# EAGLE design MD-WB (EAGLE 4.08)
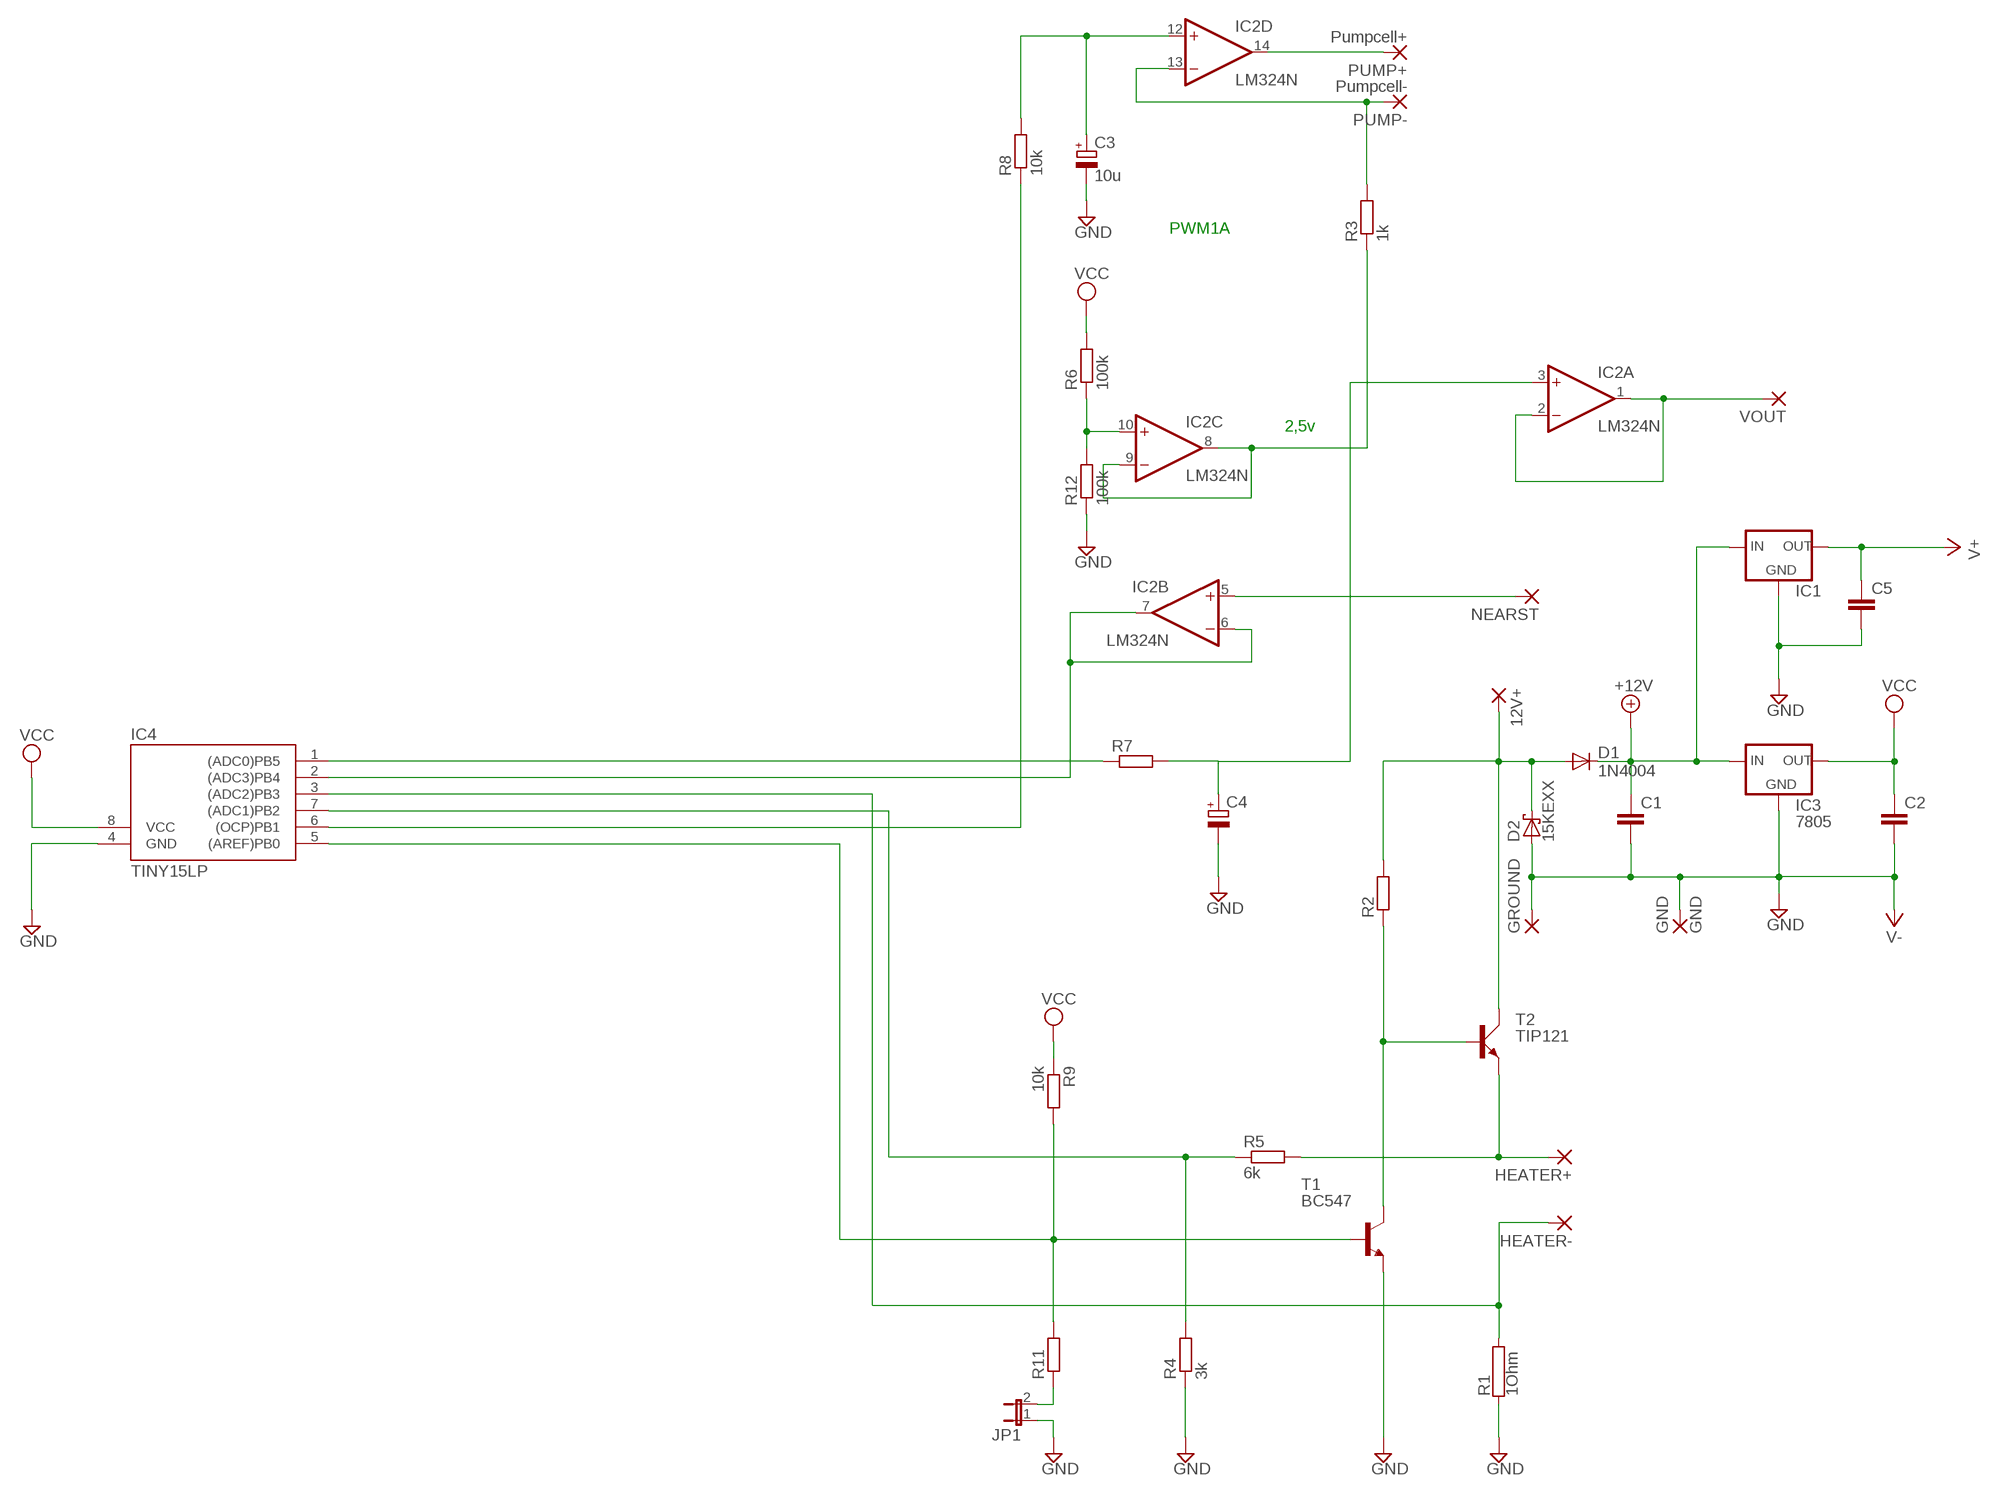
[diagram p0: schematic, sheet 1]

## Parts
12V+  2,15/1,0  [2,15/1,0]
C1  C-EU050-035X075  [C050-035X075]
C2  C-EU050-035X075  [C050-035X075]
C3  10u  CPOL-EUE2-4  [E2-4]
C4  CPOL-EUE2-4  [E2-4]
C5  C-EU050-035X075  [C050-035X075]
D1  1N4004  [DO41-10]
D2  15KEXX  [CB429-17]
GND  GND  2,54/1,0  [2,54/1,0]
GROUND  2,15/1,0  [2,15/1,0]
HEATER+  2,15/1,0  [2,15/1,0]
HEATER-  2,15/1,0  [2,15/1,0]
IC1  78LXX  [78LXX]
IC2  LM324N  [DIL14]
IC3  7805  78LXX  [78LXX]
IC4  TINY15LP  [DIL08]
JP1  JP1E  [JP1]
NEARST  2,15/1,0  [2,15/1,0]
PUMP+  Pumpcell+  2,54/1,0  [2,54/1,0]
PUMP-  Pumpcell-  2,54/1,0  [2,54/1,0]
R1  1Ohm  RKH214-8R  [KH214R-8]
R2  R-EU_0207/7  [0207/7]
R3  1k  R-EU_0207/7  [0207/7]
R4  3k  R-EU_0207/7  [0207/7]
R5  6k  R-EU_0207/7  [0207/7]
R6  100k  R-EU_0207/7  [0207/7]
R7  R-EU_0207/7  [0207/7]
R8  10k  R-EU_0207/7  [0207/7]
R9  10k  R-EU_0207/7  [0207/7]
R11  R-EU_0207/7  [0207/7]
R12  100k  R-EU_0207/7  [0207/7]
T1  BC547  [TO92]
T2  TIP121  MJE3055  [TO220AV]
VOUT  2,54/1,0  [2,54/1,0]

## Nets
+12V: C1.1 D1.C IC1.IN IC3.IN
GND: C1.2 C2.2 C3.- C4.- C5.2 D2.A GND.1(P) GROUND.1(P) IC1.GND IC3.GND IC4.4(GND) JP1.1 R1.1 R4.1 R12.1 T1.1(E) ; supply symbol labelled V-
N$1: IC2.13(D:-IN) PUMP-.1(P) R3.2
N$2: IC4.5((AREF)PB0) R9.2 R11.2 T1.2(B)
N$3: IC2.10(C:+IN) R6.1 R12.2
N$4: IC4.6((OCP)PB1) R8.1
N$5: C4.+ IC2.3(A:+IN) R7.2
N$6: R2.1 T1.3(C) T2.B
N$7: IC2.8(C:OUT) IC2.9(C:-IN) R3.1
N$8: IC2.1(A:OUT) IC2.2(A:-IN) VOUT.1(P)
N$9: C3.+ IC2.12(D:+IN) R8.2
N$10: IC4.1((ADC0)PB5) R7.1
N$11: IC2.6(B:-IN) IC2.7(B:OUT) IC4.2((ADC3)PB4)
N$13: JP1.2 R11.1
N$14: 12V+.1(P) D1.A D2.C R2.2 T2.C
N$26: IC4.7((ADC1)PB2) R4.2 R5.1
N$30: IC2.14(D:OUT) PUMP+.1(P)
N$31: HEATER-.1(P) IC4.3((ADC2)PB3) R1.2
N$36: IC2.5(B:+IN) NEARST.1(P)
N$37: HEATER+.1(P) R5.2 T2.E
V+: C5.1 IC1.OUT
VCC: C2.1 IC3.OUT IC4.8(VCC) R6.2 R9.1

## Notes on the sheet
- PWM1A
- 2,5v

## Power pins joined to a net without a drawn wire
GND: IC2.11(P:V-)
V+: IC2.4(P:V+)

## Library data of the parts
12V+ GROUND HEATER+ HEATER- NEARST = wirepad:2,15/1,0: THROUGH-HOLE PAD
C1 C2 C5 = rcl:C-EU: CAPACITOR, European symbol
C3 C4 = rcl:CPOL-EU: POLARIZED CAPACITOR, European symbol
D1 = diode:1N4004: DIODE
D2 = diode:15KEXX: DIODE
GND PUMP+ PUMP- VOUT = wirepad:2,54/1,0: THROUGH-HOLE PAD
IC1 IC3 = v-reg:78LXX: VOLTAGE REGULATOR
IC2 = linear:LM324: OP AMP
IC4 = atmel:TINY15L: MICROCONTROLLER 2.7 V 1 Kbytes FLASH 64 bytes EEPROM 4-channel 10 bit ADC
JP1 = jumper:JP1E: JUMPER
R1 = resistor-power:R: Power Resitor
R2-R9 R11 R12 = rcl:R-EU_: RESISTOR, European symbol
T1 = transistor-npn:BC547: NPN TRANSISTOR
T2 = transistor-power:MJE3055: NPN TRANSISTOR

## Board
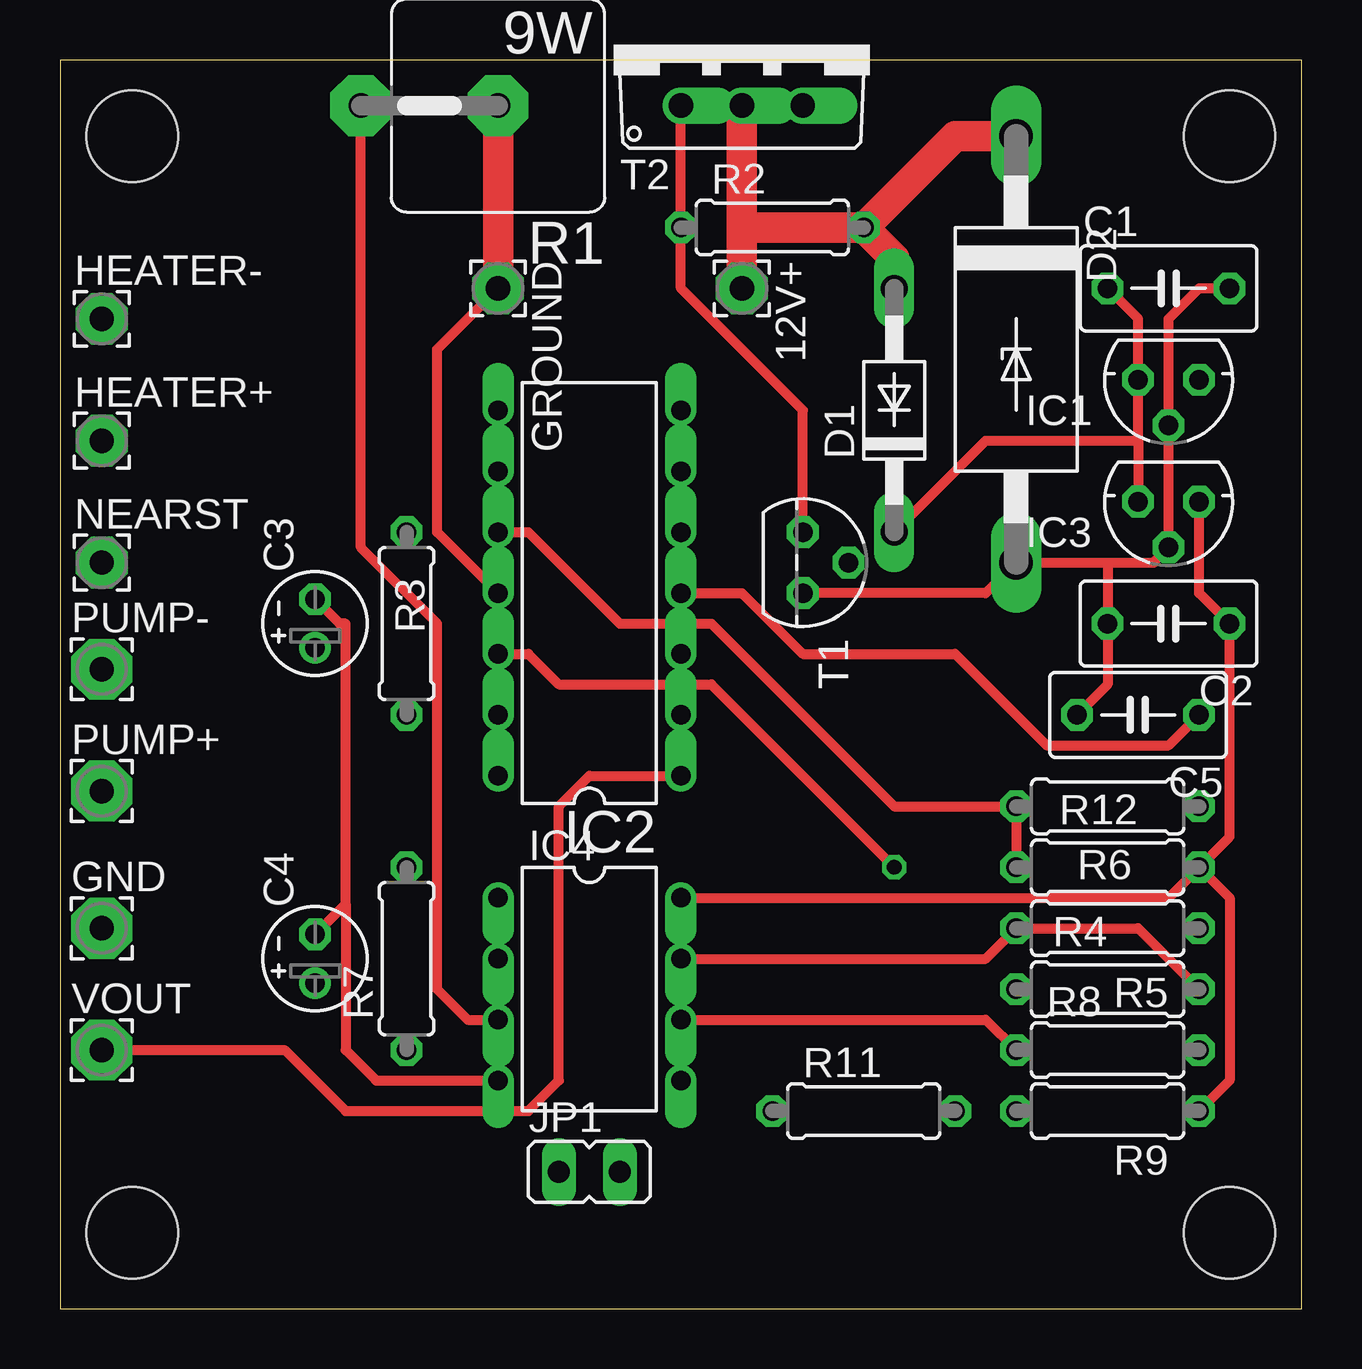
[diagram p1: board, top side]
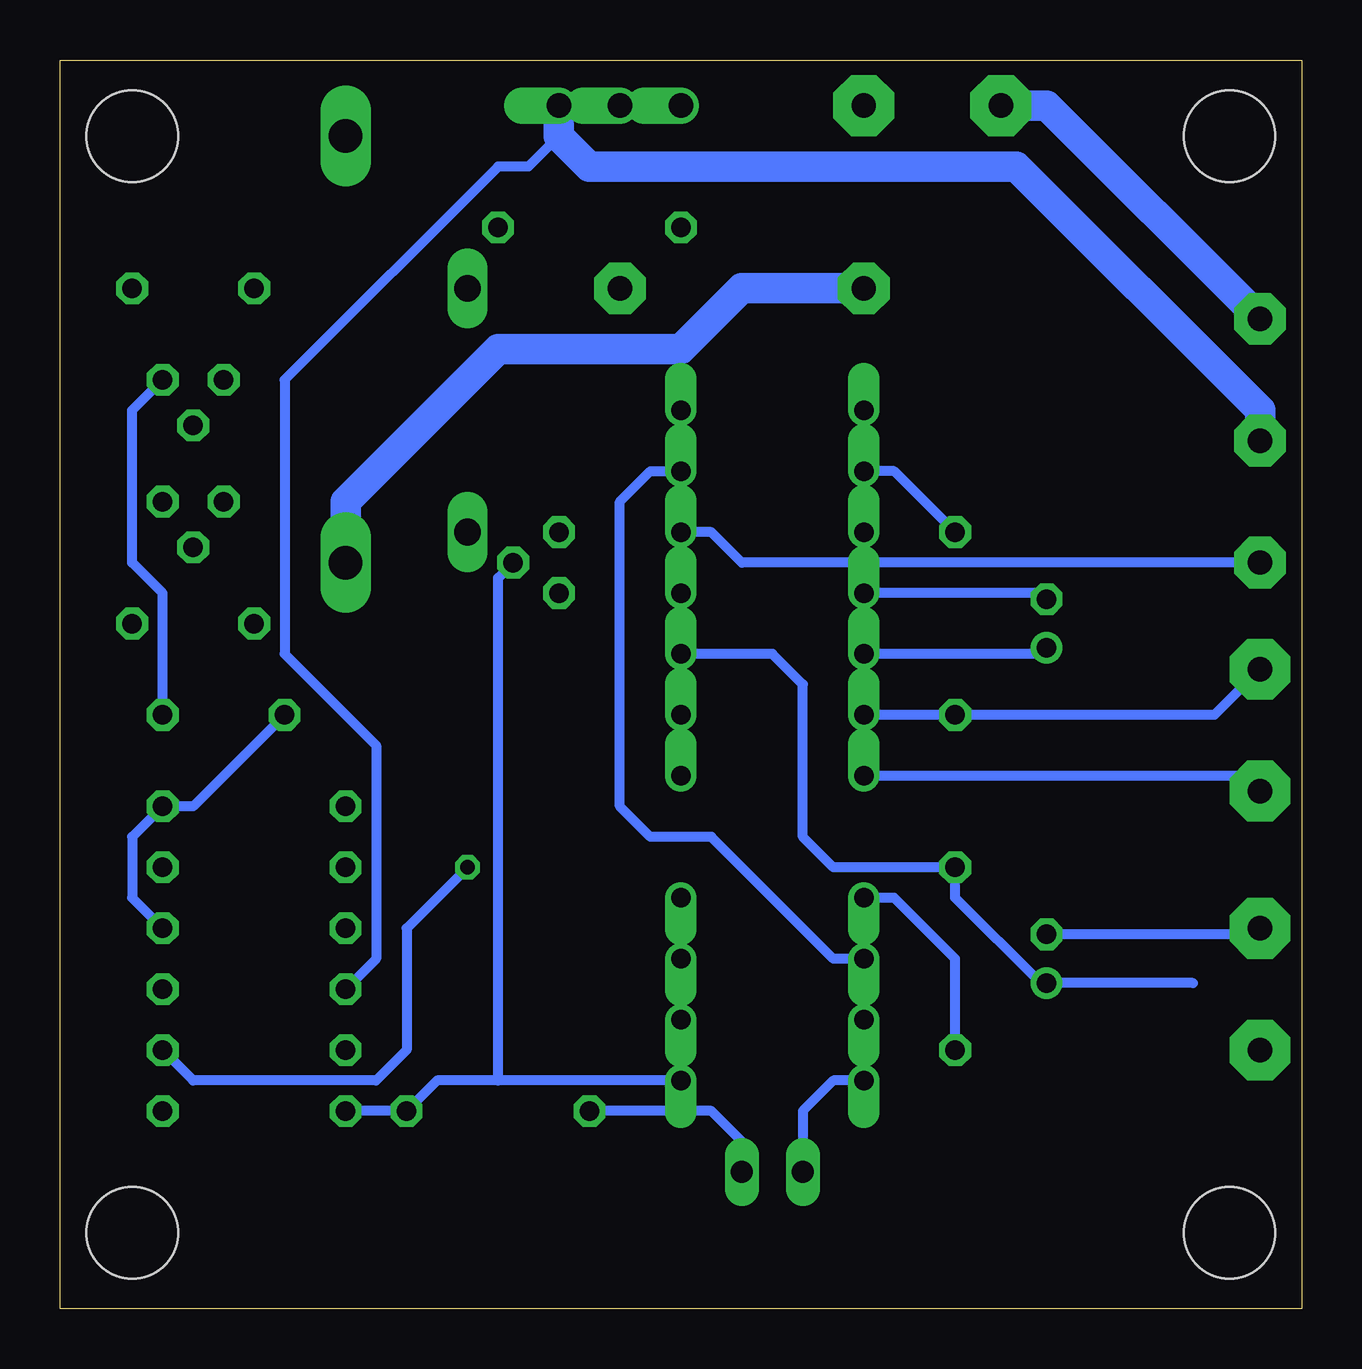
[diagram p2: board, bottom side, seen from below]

Size 51.74 x 52.06 mm. Coordinates in mm from the lower left corner, seen from the top.
Outline: 0,0 51.74,0 51.74,52.06 0,52.06 0,0
Copper layers used: Top, Bottom
Holes 3.81 mm at 3.01,48.89 3.01,3.17 48.73,3.17 48.73,48.89

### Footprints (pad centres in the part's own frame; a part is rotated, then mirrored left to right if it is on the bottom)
2,15/1,0 = drill 1.016 pad 2.159 octagon: 1 0,0
C050-035X075 = drill 0.813 octagon: 1 -2.54,0; 2 2.54,0
E2-4 = drill 0.813 pad 1.27 round: + -1.016,0 | drill 0.813 pad 1.27 octagon: - 1.016,0
DO41-10 = drill 1.118 long: A 5.08,0; C -5.08,0
CB429-17 = drill 1.397 long: A 8.89,0; C -8.89,0
2,54/1,0 = drill 1.016 pad 2.54 octagon: 1 0,0
78LXX = drill 0.813 octagon: GND 0,1.905; IN 1.27,0; OUT -1.27,0
DIL14 = drill 0.813 offset: 1 -7.62,-3.81; 2 -5.08,-3.81; 3 -2.54,-3.81; 4 0,-3.81; 5 2.54,-3.81; 6 5.08,-3.81; 7 7.62,-3.81; 8 7.62,3.81; 9 5.08,3.81; 10 2.54,3.81; 11 0,3.81; 12 -2.54,3.81; 13 -5.08,3.81; 14 -7.62,3.81
DIL08 = drill 0.813 offset: 1 -3.81,-3.81; 2 -1.27,-3.81; 3 1.27,-3.81; 4 3.81,-3.81; 5 3.81,3.81; 6 1.27,3.81; 7 -1.27,3.81; 8 -3.81,3.81
JP1 = drill 0.914 long: 1 0,-1.27; 2 0,1.27
KH214R-8 = drill 1.016 pad 2.54 octagon: 1 -2.54,0; 2 3.175,0
0207/7 = drill 0.813 octagon: 1 -3.81,0; 2 3.81,0
TO92 = drill 0.813 octagon: 1 1.27,0; 2 0,1.905; 3 -1.27,0
TO220AV = drill 1.016 offset: B -2.54,-2.54; C 0,-2.54; E 2.54,-2.54

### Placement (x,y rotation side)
12V+  28.41,42.54 270 top
C1  46.19,42.54 0 top
C2  46.19,28.57 180 top
C3  10.63,28.57 90 top
C4  10.63,14.6 90 top
C5  44.92,24.76 180 top
D1  34.76,37.46 90 top
D2  39.84,40 270 top
GND  1.74,15.87 0 top
GROUND  18.25,42.54 270 top
HEATER+  1.74,36.19 0 top
HEATER-  1.74,41.27 0 top
IC1  46.19,38.73 180 top
IC2  22.06,29.84 90 top
IC3  46.19,33.65 180 top
IC4  22.06,13.33 270 top
JP1  22.06,5.71 270 top
NEARST  1.74,31.11 0 top
PUMP+  1.74,21.58 0 top
PUMP-  1.74,26.66 0 top
R1  15.71,50.16 180 top
R2  29.68,45.08 0 top
R3  14.44,28.57 270 top
R4  43.65,15.87 180 top
R5  43.65,13.33 180 top
R6  43.65,18.41 0 top
R7  14.44,14.6 90 top
R8  43.65,10.79 0 top
R9  43.65,8.25 180 top
R11  33.49,8.25 0 top
R12  43.65,20.95 180 top
T1  30.95,31.11 270 top
T2  28.41,52.7 0 top
VOUT  1.74,10.79 0 top

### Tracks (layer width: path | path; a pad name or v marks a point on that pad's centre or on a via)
+12V
  Top 0.406: D1.C 38.57,36.19 44.92,36.19 | C1.1 44.92,41.27 IC1.IN 44.92,36.19 | 44.92,36.19 IC3.IN
GND
  Top 0.406: T1.1 38.57,29.84 D2.A 43.65,31.11 | C1.2 47.46,42.54 46.19,41.27 IC1.GND IC3.GND 45.55,31.11 43.65,31.11 | C5.2 43.65,26.03 C2.2 43.65,31.11 | C3.- 11.65,28.57 11.9,28.57 11.9,16.89 | C4.- 11.9,16.89 | 11.9,16.89 11.9,10.79 13.17,9.52 IC4.4 | GROUND.1 15.71,40 15.71,32.38 IC2.11
  Top 1.27: GROUND.1 R1.1
  Bottom 0.406: C5.2 46.19,20.95 R12.1 48.73,19.68 48.73,17.14 R4.1 | C4.- 1.99,15.62 GND.1 | C3.- 10.88,29.84 IC2.11 | IC4.4 19.52,9.52 20.79,8.25 JP1.1
  Bottom 1.27: GROUND.1 23.33,42.54 25.87,40 33.49,40 39.84,33.65 D2.A
N$1
  Bottom 0.406: IC2.13 R3.2 3.64,24.76 PUMP-.1
N$2
  Bottom 0.406: T1.2 33.49,30.47 33.49,9.52 | IC4.5 33.49,9.52 | R9.2 R11.2 36.03,9.52 33.49,9.52
N$3
  Top 0.406: IC2.10 19.52,32.38 23.33,28.57 27.14,28.57 34.76,20.95 R12.2 R6.1
N$4
  Top 0.406: IC4.6 38.57,12.06 R8.1
N$5
  Bottom 0.406: 4.53,13.58 C4.+ 10.88,13.58 14.44,17.14 R7.2 19.52,18.41 20.79,19.68 20.79,26.03 22.06,27.3 IC2.3
N$6
  Top 0.406: T2.B R2.1 25.87,42.54 30.95,37.46 T1.3
N$7
  Bottom 0.406: R3.1 16.98,34.92 IC2.9 IC2.8
N$8
  Top 0.406: IC2.1 22.06,22.22 20.79,20.95 20.79,9.52 19.52,8.25 11.9,8.25 9.36,10.79 VOUT.1
  Bottom 0.406: IC2.1 IC2.2
N$9  (via drill 0.61)
  Top 0.406: IC2.12 19.52,27.3 20.79,26.03 27.14,26.03 v34.76,18.41
  Bottom 0.406: C3.+ 10.88,27.3 IC2.12 | R8.2 46.19,9.52 38.57,9.52 37.3,10.79 37.3,15.87 v34.76,18.41
N$10
  Bottom 0.406: R7.1 14.44,14.6 16.98,17.14 IC4.1
N$11
  Bottom 0.406: IC2.7 IC2.6 27.14,34.92 28.41,33.65 28.41,20.95 27.14,19.68 24.6,19.68 19.52,14.6 IC4.2
N$13
  Bottom 0.406: R11.1 24.6,8.25 23.33,6.98 JP1.2
N$14
  Top 1.27: 28.41,45.08 T2.C | 12V+.1 28.41,45.08 | D2.C 37.3,48.89 R2.2 | D1.A 34.76,43.81 R2.2 | 28.41,45.08 R2.2
N$26
  Top 0.406: IC4.7 38.57,14.6 R4.2 44.92,15.87 R5.1
N$30
  Bottom 0.406: PUMP+.1 2.38,22.22 IC2.14
N$31
  Top 0.406: R1.2 12.54,31.74 15.71,28.57 15.71,13.33 16.98,12.06 IC4.3
  Bottom 1.27: R1.2 10.63,50.16 HEATER-.1
N$36
  Bottom 0.406: NEARST.1 23.33,31.11 24.6,32.38 IC2.5
N$37
  Bottom 0.406: R5.2 38.57,14.6 38.57,23.49 42.38,27.3 42.38,38.73 33.49,47.62 32.22,47.62 30.95,48.89
  Bottom 1.27: T2.E 30.95,48.89 29.68,47.62 11.9,47.62 1.74,37.46 HEATER+.1
V+
  Top 0.406: IC2.4 28.41,29.84 30.95,27.3 37.3,27.3 41.11,23.49 46.19,23.49 C5.1
  Bottom 0.406: IC1.OUT 48.73,37.46 48.73,31.11 47.46,29.84 C5.1
VCC
  Top 0.406: IC3.OUT 47.46,29.84 C2.1 48.73,19.68 R6.2 | IC4.8 46.19,17.14 R6.2 | R9.1 48.73,9.52 48.73,17.14 R6.2

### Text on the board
tNames: (C) Jörgen Karlsson 2003 | MD-WB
